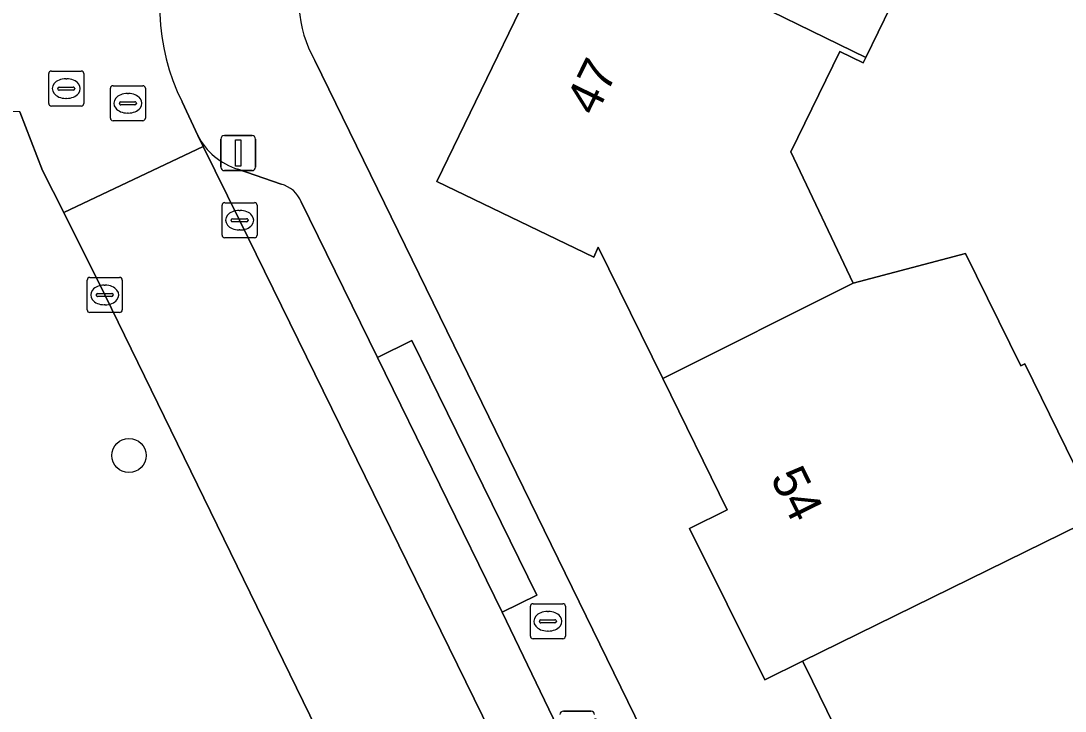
# Model space of a CAD drawing. Extents: x 160455 to 162082, y 388339 to 389736.
# Drawn here: x 160618.42 to 160648.24, y 388930.88 to 388950.59 of the extents above; entities that cross this region are included whole.
import ezdxf

# ---------------------------------------------------------------- set-up
doc = ezdxf.new("R2010")
doc.units = 0
for name, color, linetype in [('IMGEO_Boom', 7, 'Continuous'), ('IMGEO_Brandkraan', 7, 'Continuous'), ('IMGEO_Erf', 7, 'Continuous'), ('IMGEO_Groenvoorziening', 7, 'Continuous'), ('IMGEO_Kolk', 7, 'Continuous'), ('IMGEO_Lichtmast', 7, 'Continuous'), ('IMGEO_Pand', 7, 'Continuous'), ('IMGEO_Pand_nummerreeks', 7, 'Continuous'), ('IMGEO_Parkeervlak_open', 7, 'Continuous'), ('IMGEO_Rijbaan_lokaal_gesloten', 7, 'Continuous'), ('IMGEO_Rijbaan_lokaal_open', 7, 'Continuous'), ('IMGEO_Rioolput', 7, 'Continuous'), ('IMGEO_Voetpad_open', 7, 'Continuous')]:
    doc.layers.add(name, color=color, linetype=linetype)

msp = doc.modelspace()

# ---------------------------------------------------------------- linework, layer by layer
at = {"layer": 'IMGEO_Boom'}
msp.add_circle((160621.504, 388938.181), 0.489, dxfattribs=at)
at = {"layer": 'IMGEO_Brandkraan'}
for p, q in [((160632.967, 388933.024), (160632.967, 388933.876)), ((160633.042, 388933.95), (160633.894, 388933.95)), ((160633.455, 388933.73), (160633.48, 388933.73)), ((160633.968, 388933.876), (160633.968, 388933.024)), ((160633.226, 388933.444), (160633.226, 388933.456)), ((160633.664, 388933.407), (160633.266, 388933.407)), ((160633.269, 388933.493), (160633.667, 388933.493)), ((160633.71, 388933.456), (160633.71, 388933.444)), ((160633.478, 388933.17), (160633.453, 388933.17)), ((160633.894, 388932.95), (160633.042, 388932.95))]:
    msp.add_line(p, q, dxfattribs=at)
for points in [[(160632.967, 388933.024), (160632.967, 388933.876)], [(160633.042, 388933.95), (160633.894, 388933.95)], [(160633.968, 388933.876), (160633.968, 388933.024)], [(160633.894, 388932.95), (160633.042, 388932.95)]]:
    msp.add_lwpolyline(points, dxfattribs=at)
for centre, radius, start, end in [((160633.044, 388933.874), 0.0765, 91.552, 178.448), ((160633.044, 388933.874), 0.0765, 91.552, 178.448), ((160633.892, 388933.874), 0.0765, 1.552, 88.448), ((160633.892, 388933.874), 0.0765, 1.552, 88.448), ((160633.266, 388933.453), 0.0403, 85.8775, 175.7526), ((160633.263, 388933.443), 0.0366, 178.938, 274.7102), ((160633.667, 388933.45), 0.043, 264.8664, 352.4533), ((160633.671, 388933.455), 0.0386, 1.7309, 96.639), ((160633.044, 388933.026), 0.0765, 181.552, 268.448), ((160633.044, 388933.026), 0.0765, 181.552, 268.448), ((160633.892, 388933.026), 0.0765, 271.552, 358.448), ((160633.892, 388933.026), 0.0765, 271.552, 358.448)]:
    msp.add_arc(centre, radius, start, end, dxfattribs=at)
for centre, major_axis, ratio, start_param, end_param in [((160633.454, 388933.45), (-0.387, 0.002), 0.722429, 4.712389, 7.853982), ((160633.479, 388933.45), (-0.39, 0.002), 0.717154, 1.570796, 4.712389)]:
    msp.add_ellipse(centre, major_axis=major_axis, ratio=ratio, start_param=start_param, end_param=end_param, dxfattribs=at)
at = {"layer": 'IMGEO_Erf'}
for points in [[(160642.261, 388929.203), (160640.812, 388932.164), (160640.74, 388932.31), (160639.662, 388931.781), (160637.512, 388936.098), (160638.587, 388936.633), (160636.748, 388940.376), (160634.904, 388944.13), (160634.778, 388943.847), (160630.294, 388946.009), (160632.83, 388951.225), (160633.963, 388953.556), (160634.037, 388953.708), (160632.959, 388954.235), (160635.064, 388958.553), (160636.143, 388958.027), (160637.92, 388961.678), (160636.833, 388962.209), (160639.038, 388966.686), (160640.126, 388966.159), (160641.323, 388968.632), (160641.871, 388969.763), (160641.943, 388969.912), (160640.858, 388970.443)], [(160650.403, 388965.772), (160646.417, 388957.524), (160644.662, 388953.893), (160642.542, 388949.546), (160642.467, 388949.393), (160641.805, 388949.715), (160640.408, 388946.847), (160642.188, 388943.101), (160645.394, 388943.951), (160646.969, 388940.74), (160647.085, 388940.797), (160649.209, 388936.465)], [(160626.809, 388949.464), (160655.206, 388891.323)]]:
    msp.add_lwpolyline(points, dxfattribs=at)
msp.add_arc((160629.931, 388951.222), 3.583, 159.5475, 209.3809, dxfattribs=at)
at = {"layer": 'IMGEO_Groenvoorziening'}
msp.add_lwpolyline([(160571.444, 388750), (160571.754, 388750.166), (160572.065, 388750.329), (160607.803, 388767.824), (160687.247, 388806.714), (160686.973, 388807.274), (160686.045, 388809.17), (160684.847, 388811.633), (160677.31, 388827.125), (160668.584, 388844.978), (160659.808, 388862.897), (160659.071, 388864.445), (160648.25, 388886.548), (160638.47, 388906.585), (160629.688, 388924.586), (160620.814, 388942.765), (160619.643, 388945.116), (160619.032, 388946.319), (160618.392, 388947.991), (160617.059, 388948.01), (160612.318, 388945.878)], dxfattribs=at)
at = {"layer": 'IMGEO_Kolk'}
for p, q in [((160624.163, 388944.474), (160624.163, 388945.326)), ((160624.238, 388945.4), (160625.09, 388945.4)), ((160625.164, 388945.326), (160625.164, 388944.474)), ((160624.651, 388945.18), (160624.676, 388945.18)), ((160624.422, 388944.894), (160624.422, 388944.906)), ((160624.86, 388944.857), (160624.462, 388944.857)), ((160624.465, 388944.943), (160624.863, 388944.943)), ((160624.906, 388944.906), (160624.906, 388944.894)), ((160624.674, 388944.62), (160624.649, 388944.62)), ((160625.09, 388944.4), (160624.238, 388944.4)), ((160620.386, 388943.265), (160621.238, 388943.265)), ((160620.311, 388942.339), (160620.311, 388943.191)), ((160620.799, 388943.045), (160620.824, 388943.045)), ((160621.312, 388943.191), (160621.312, 388942.339)), ((160620.57, 388942.759), (160620.57, 388942.771)), ((160621.008, 388942.722), (160620.61, 388942.722)), ((160620.613, 388942.808), (160621.011, 388942.808)), ((160621.054, 388942.771), (160621.054, 388942.759)), ((160620.822, 388942.485), (160620.797, 388942.485)), ((160621.238, 388942.265), (160620.386, 388942.265))]:
    msp.add_line(p, q, dxfattribs=at)
for points in [[(160624.163, 388944.474), (160624.163, 388945.326)], [(160624.238, 388945.4), (160625.09, 388945.4)], [(160625.164, 388945.326), (160625.164, 388944.474)], [(160625.09, 388944.4), (160624.238, 388944.4)], [(160620.386, 388943.265), (160621.238, 388943.265)], [(160620.311, 388942.339), (160620.311, 388943.191)], [(160621.312, 388943.191), (160621.312, 388942.339)], [(160621.238, 388942.265), (160620.386, 388942.265)]]:
    msp.add_lwpolyline(points, dxfattribs=at)
for centre, radius, start, end in [((160624.24, 388945.324), 0.0765, 91.552, 178.448), ((160624.24, 388945.324), 0.0765, 91.552, 178.448), ((160625.088, 388945.324), 0.0765, 1.552, 88.448), ((160625.088, 388945.324), 0.0765, 1.552, 88.448), ((160624.462, 388944.903), 0.0403, 85.8775, 175.7526), ((160624.459, 388944.893), 0.0366, 178.938, 274.7102), ((160624.863, 388944.9), 0.043, 264.8664, 352.4533), ((160624.867, 388944.905), 0.0386, 1.7309, 96.639), ((160624.24, 388944.476), 0.0765, 181.552, 268.448), ((160624.24, 388944.476), 0.0765, 181.552, 268.448), ((160625.088, 388944.476), 0.0765, 271.552, 358.448), ((160625.088, 388944.476), 0.0765, 271.552, 358.448), ((160620.388, 388943.189), 0.0765, 91.552, 178.448), ((160620.388, 388943.189), 0.0765, 91.552, 178.448), ((160621.236, 388943.189), 0.0765, 1.552, 88.448), ((160621.236, 388943.189), 0.0765, 1.552, 88.448), ((160620.61, 388942.768), 0.0403, 85.8775, 175.7526), ((160620.607, 388942.758), 0.0366, 178.938, 274.7102), ((160621.011, 388942.765), 0.043, 264.8664, 352.4533), ((160621.015, 388942.77), 0.0386, 1.7309, 96.639), ((160620.388, 388942.341), 0.0765, 181.552, 268.448), ((160620.388, 388942.341), 0.0765, 181.552, 268.448), ((160621.236, 388942.341), 0.0765, 271.552, 358.448), ((160621.236, 388942.341), 0.0765, 271.552, 358.448)]:
    msp.add_arc(centre, radius, start, end, dxfattribs=at)
for centre, major_axis, ratio, start_param, end_param in [((160624.65, 388944.9), (-0.387, 0.002), 0.722429, 4.712389, 7.853982), ((160624.675, 388944.9), (-0.39, 0.002), 0.717154, 1.570796, 4.712389), ((160620.798, 388942.765), (-0.387, 0.002), 0.722429, 4.712389, 7.853982), ((160620.823, 388942.765), (-0.39, 0.002), 0.717154, 1.570796, 4.712389)]:
    msp.add_ellipse(centre, major_axis=major_axis, ratio=ratio, start_param=start_param, end_param=end_param, dxfattribs=at)
at = {"layer": 'IMGEO_Lichtmast'}
for p, q in [((160624.128, 388946.415), (160624.128, 388947.215)), ((160624.128, 388947.215), (160624.128, 388946.415)), ((160624.228, 388947.315), (160625.018, 388947.315)), ((160625.018, 388947.315), (160624.228, 388947.315)), ((160625.118, 388947.215), (160625.118, 388946.415)), ((160625.118, 388946.415), (160625.118, 388947.215)), ((160625.018, 388946.315), (160624.228, 388946.315)), ((160624.228, 388946.315), (160625.018, 388946.315)), ((160633.909, 388930.884), (160634.699, 388930.884)), ((160634.699, 388930.884), (160633.909, 388930.884))]:
    msp.add_line(p, q, dxfattribs=at)
msp.add_lwpolyline([(160624.548, 388947.19), (160624.698, 388947.19), (160624.698, 388946.44), (160624.548, 388946.44), (160624.548, 388947.19)], dxfattribs=at)
for centre, start, end in [((160624.228, 388947.215), 90, 180), ((160624.228, 388947.215), 90, 180), ((160625.018, 388947.215), 0, 90), ((160625.018, 388947.215), 360, 90), ((160624.228, 388946.415), 180, 270), ((160624.228, 388946.415), 180, 270), ((160625.018, 388946.415), 270, 0), ((160625.018, 388946.415), 270, 0), ((160633.909, 388930.784), 90, 180), ((160633.909, 388930.784), 90, 180), ((160634.699, 388930.784), 0, 90), ((160634.699, 388930.784), 360, 90)]:
    msp.add_arc(centre, 0.1, start, end, dxfattribs=at)
at = {"layer": 'IMGEO_Pand'}
for points in [[(160646.417, 388957.524), (160637.92, 388961.678), (160636.143, 388958.027), (160635.064, 388958.553), (160632.959, 388954.235), (160634.037, 388953.708), (160642.542, 388949.546), (160644.662, 388953.893)], [(160642.542, 388949.546), (160634.037, 388953.708), (160633.963, 388953.556), (160632.83, 388951.225), (160630.294, 388946.009), (160634.778, 388943.847), (160634.904, 388944.13), (160636.748, 388940.376), (160642.188, 388943.101), (160640.408, 388946.847), (160641.805, 388949.715), (160642.467, 388949.393)], [(160647.085, 388940.797), (160646.969, 388940.74), (160645.394, 388943.951), (160642.188, 388943.101), (160636.748, 388940.376), (160638.587, 388936.633), (160637.512, 388936.098), (160639.662, 388931.781), (160640.74, 388932.31), (160649.209, 388936.465)], [(160649.209, 388936.465), (160640.74, 388932.31), (160640.812, 388932.164), (160642.261, 388929.203), (160642.584, 388928.544), (160641.506, 388928.017), (160643.618, 388923.698), (160644.696, 388924.225), (160653.176, 388928.373), (160651.052, 388932.706), (160649.284, 388936.312)]]:
    msp.add_lwpolyline(points, close=True, dxfattribs=at)
at = {"layer": 'IMGEO_Parkeervlak_open'}
for points in [[(160623.469, 388947.315), (160623.621, 388947.008), (160624.663, 388944.899), (160632.797, 388928.304), (160634.395, 388929.087), (160633.852, 388930.189), (160632.159, 388933.706), (160628.597, 388940.979)], [(160625.847, 388945.925), (160624.611, 388946.36)], [(160628.597, 388940.979), (160626.424, 388945.422)]]:
    msp.add_lwpolyline(points, dxfattribs=at)
for centre, radius, start, end in [((160625.181, 388948.202), 1.929, 207.3945, 252.7973), ((160625.66, 388945.128), 0.819, 21.0495, 76.7899)]:
    msp.add_arc(centre, radius, start, end, dxfattribs=at)
at = {"layer": 'IMGEO_Rijbaan_lokaal_gesloten'}
msp.add_lwpolyline([(160638.282, 388917.069), (160636.489, 388920.744), (160634.263, 388925.305), (160633.637, 388926.589), (160632.797, 388928.304), (160624.663, 388944.899), (160623.621, 388947.008), (160619.643, 388945.116), (160620.814, 388942.765), (160629.688, 388924.586), (160638.47, 388906.585), (160648.25, 388886.548), (160652.243, 388888.526), (160651.242, 388890.581), (160642.445, 388908.538), (160641.968, 388909.516), (160640.404, 388912.721)], close=True, dxfattribs=at)
at = {"layer": 'IMGEO_Rijbaan_lokaal_open'}
msp.add_lwpolyline([(160618.392, 388947.991), (160619.032, 388946.319), (160619.643, 388945.116), (160623.621, 388947.008), (160623.469, 388947.315), (160623.024, 388948.279)], dxfattribs=at)
msp.add_arc((160628.421, 388950.989), 6.039, 157.0698, 206.6634, dxfattribs=at)
at = {"layer": 'IMGEO_Rioolput'}
for p, q in [((160619.213, 388948.232), (160619.213, 388949.084)), ((160619.288, 388949.158), (160620.14, 388949.158)), ((160619.701, 388948.938), (160619.726, 388948.938)), ((160620.214, 388949.084), (160620.214, 388948.232)), ((160619.472, 388948.652), (160619.472, 388948.664)), ((160619.91, 388948.615), (160619.512, 388948.615)), ((160619.515, 388948.701), (160619.913, 388948.701)), ((160619.956, 388948.664), (160619.956, 388948.652)), ((160620.973, 388947.813), (160620.973, 388948.665)), ((160621.048, 388948.739), (160621.9, 388948.739)), ((160621.974, 388948.665), (160621.974, 388947.813)), ((160619.724, 388948.378), (160619.699, 388948.378)), ((160621.275, 388948.282), (160621.673, 388948.282)), ((160621.461, 388948.519), (160621.486, 388948.519)), ((160620.14, 388948.158), (160619.288, 388948.158)), ((160621.232, 388948.233), (160621.232, 388948.245)), ((160621.67, 388948.196), (160621.272, 388948.196)), ((160621.716, 388948.245), (160621.716, 388948.233)), ((160621.9, 388947.739), (160621.048, 388947.739)), ((160621.484, 388947.959), (160621.459, 388947.959))]:
    msp.add_line(p, q, dxfattribs=at)
for points in [[(160619.213, 388948.232), (160619.213, 388949.084)], [(160619.288, 388949.158), (160620.14, 388949.158)], [(160620.214, 388949.084), (160620.214, 388948.232)], [(160620.973, 388947.813), (160620.973, 388948.665)], [(160621.048, 388948.739), (160621.9, 388948.739)], [(160621.974, 388948.665), (160621.974, 388947.813)], [(160620.14, 388948.158), (160619.288, 388948.158)], [(160621.9, 388947.739), (160621.048, 388947.739)]]:
    msp.add_lwpolyline(points, dxfattribs=at)
for centre, radius, start, end in [((160619.29, 388949.082), 0.0765, 91.552, 178.448), ((160619.29, 388949.082), 0.0765, 91.552, 178.448), ((160620.138, 388949.082), 0.0765, 1.552, 88.448), ((160620.138, 388949.082), 0.0765, 1.552, 88.448), ((160619.512, 388948.661), 0.0403, 85.8775, 175.7526), ((160619.509, 388948.651), 0.0366, 178.938, 274.7102), ((160619.913, 388948.658), 0.043, 264.8664, 352.4533), ((160619.917, 388948.663), 0.0386, 1.7309, 96.639), ((160621.05, 388948.663), 0.0765, 91.552, 178.448), ((160621.05, 388948.663), 0.0765, 91.552, 178.448), ((160621.898, 388948.663), 0.0765, 1.552, 88.448), ((160621.898, 388948.663), 0.0765, 1.552, 88.448), ((160621.272, 388948.242), 0.0403, 85.8775, 175.7526), ((160621.677, 388948.244), 0.0386, 1.7309, 96.639), ((160619.29, 388948.234), 0.0765, 181.552, 268.448), ((160619.29, 388948.234), 0.0765, 181.552, 268.448), ((160620.138, 388948.234), 0.0765, 271.552, 358.448), ((160620.138, 388948.234), 0.0765, 271.552, 358.448), ((160621.269, 388948.232), 0.0366, 178.938, 274.7102), ((160621.673, 388948.239), 0.043, 264.8664, 352.4533), ((160621.05, 388947.815), 0.0765, 181.552, 268.448), ((160621.05, 388947.815), 0.0765, 181.552, 268.448), ((160621.898, 388947.815), 0.0765, 271.552, 358.448), ((160621.898, 388947.815), 0.0765, 271.552, 358.448)]:
    msp.add_arc(centre, radius, start, end, dxfattribs=at)
for centre, major_axis, ratio, start_param, end_param in [((160619.7, 388948.658), (-0.387, 0.002), 0.722429, 4.712389, 7.853982), ((160619.725, 388948.658), (-0.39, 0.002), 0.717154, 1.570796, 4.712389), ((160621.46, 388948.239), (-0.387, 0.002), 0.722429, 4.712389, 7.853982), ((160621.485, 388948.239), (-0.39, 0.002), 0.717154, 1.570796, 4.712389)]:
    msp.add_ellipse(centre, major_axis=major_axis, ratio=ratio, start_param=start_param, end_param=end_param, dxfattribs=at)
at = {"layer": 'IMGEO_Voetpad_open'}
for points in [[(160658.572, 388882.915), (160655.206, 388891.323), (160626.809, 388949.464)], [(160623.024, 388948.279), (160623.469, 388947.315)], [(160624.611, 388946.36), (160625.847, 388945.925)], [(160626.424, 388945.422), (160628.597, 388940.979), (160629.585, 388941.463), (160633.147, 388934.19), (160632.159, 388933.706), (160633.852, 388930.189), (160634.839, 388930.675), (160637.094, 388926.101), (160636.107, 388925.615), (160637.815, 388922.106), (160638.803, 388922.59), (160641.045, 388918.009), (160640.057, 388917.525), (160641.779, 388914.011), (160642.766, 388914.496), (160645.021, 388909.911), (160644.034, 388909.426), (160652.824, 388891.478)]]:
    msp.add_lwpolyline(points, dxfattribs=at)
msp.add_lwpolyline([(160632.159, 388933.706), (160633.147, 388934.19), (160629.585, 388941.463), (160628.597, 388940.979)], close=True, dxfattribs=at)
for centre, radius, start, end in [((160628.421, 388950.989), 6.039, 157.0698, 206.6634), ((160629.931, 388951.222), 3.583, 159.5475, 209.3809), ((160625.181, 388948.202), 1.929, 207.3945, 252.7973), ((160625.66, 388945.128), 0.819, 21.0495, 76.7899)]:
    msp.add_arc(centre, radius, start, end, dxfattribs=at)

# ---------------------------------------------------------------- texts
at = {"layer": 'IMGEO_Pand_nummerreeks'}
for s, rotation, p in [('47', 64.0452, (160634.833, 388947.84)), ('54', 296.1668, (160639.807, 388937.551))]:
    msp.add_text(s, height=1, rotation=rotation, dxfattribs=at).set_placement(p)

doc.saveas('drawing.dxf')
